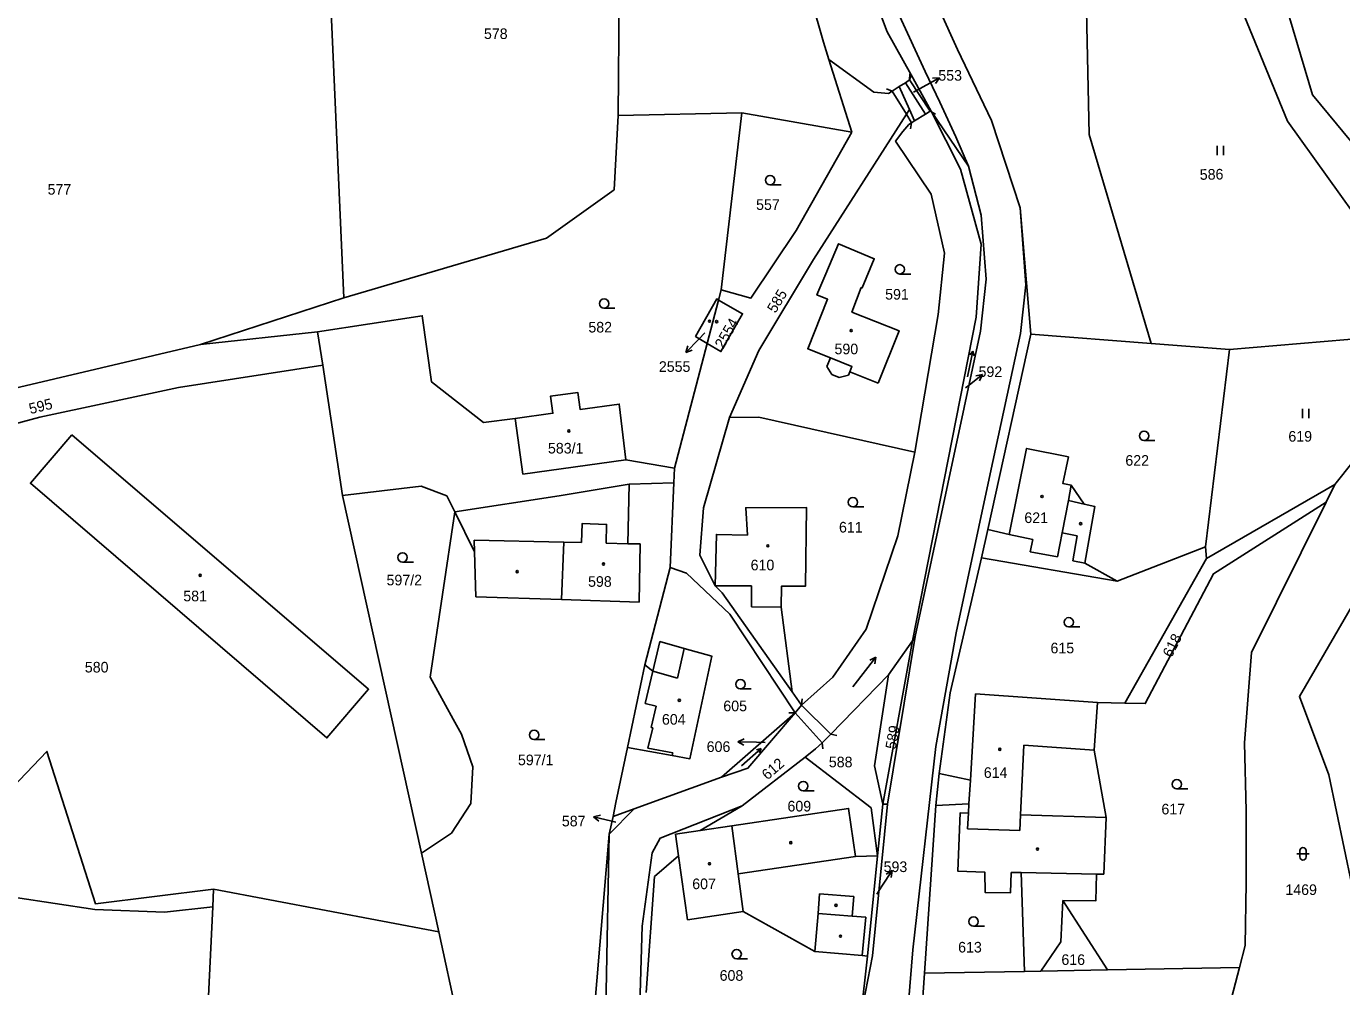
# Model space of a CAD drawing. Extents: x -520431 to -517205, y -1075927 to -1074013.
# Drawn here: x -518044.1 to -517833.2, y -1075835.4 to -1075681.5 of the extents above; entities that cross this region are included whole.
import ezdxf

# ---------------------------------------------------------------- set-up
doc = ezdxf.new("R2010")
doc.units = 0
for name, color, linetype in [('Hranice parcel', 7, 'Continuous'), ('Parcelní čísla', 7, 'Continuous'), ('Pop  PČ popisy', 7, 'Continuous'), ('Vnitřní kresba', 7, 'Continuous'), ('Značky budov', 7, 'Continuous'), ('Značky kultur', 7, 'Continuous')]:
    doc.layers.add(name, color=color, linetype=linetype)

msp = doc.modelspace()

# ---------------------------------------------------------------- linework, layer by layer
at = {"layer": 'Hranice parcel'}
for p, q in [((-517993.21, -1075725.03), (-517996.53, -1075648.79)), ((-517949.22, -1075695.82), (-517948.93, -1075661.56)), ((-517841.94, -1075696.76), (-517852.53, -1075670.8)), ((-517911.76, -1075698.48), (-517915.44, -1075686.85)), ((-517902.27, -1075689.29), (-517902.5, -1075690.13)), ((-517899.03, -1075695.13), (-517902.27, -1075689.29)), ((-517904.17, -1075691.2), (-517905.29, -1075691.92)), ((-517902.52, -1075694.85), (-517904.17, -1075691.2)), ((-517902.5, -1075690.13), (-517903.18, -1075690.57)), ((-517903.18, -1075690.57), (-517899.98, -1075695.6)), ((-517929.4, -1075695.38), (-517949.22, -1075695.82)), ((-517932.68, -1075723.77), (-517929.4, -1075695.38)), ((-517929.4, -1075695.38), (-517911.76, -1075698.48)), ((-517901.7, -1075696.68), (-517902.52, -1075694.85)), ((-517899.98, -1075695.6), (-517899.22, -1075695.12)), ((-517899.22, -1075695.12), (-517899.03, -1075695.13)), ((-517899.03, -1075695.13), (-517893.06, -1075703.93)), ((-517902.19, -1075696.98), (-517901.7, -1075696.68)), ((-517884.79, -1075710.63), (-517883.07, -1075730.86)), ((-517993.21, -1075725.03), (-517960.71, -1075715.51)), ((-518016.17, -1075732.51), (-517993.21, -1075725.03)), ((-517933.11, -1075725.4), (-517934.94, -1075732.35)), ((-517933.11, -1075725.4), (-517932.68, -1075723.77)), ((-518016.17, -1075732.51), (-517997.43, -1075730.48)), ((-517996.55, -1075735.82), (-517997.43, -1075730.48)), ((-517883.07, -1075730.86), (-517889.97, -1075762.15)), ((-517883.07, -1075730.86), (-517863.8, -1075732.34)), ((-517851.25, -1075733.31), (-517814.81, -1075730.26)), ((-517834.35, -1075754.98), (-517814.81, -1075730.26)), ((-517940.21, -1075752.33), (-517934.94, -1075732.35)), ((-517863.8, -1075732.34), (-517851.25, -1075733.31)), ((-517851.25, -1075733.31), (-517855.06, -1075764.95)), ((-517993.41, -1075756.71), (-517996.55, -1075735.82)), ((-517940.21, -1075752.33), (-517940.31, -1075754.67)), ((-517947.65, -1075764.44), (-517947.45, -1075754.88)), ((-517947.45, -1075754.88), (-517940.31, -1075754.67)), ((-517940.31, -1075754.67), (-517940.86, -1075768.28)), ((-517834.35, -1075754.98), (-517854.94, -1075766.83)), ((-517835.74, -1075757.77), (-517834.35, -1075754.98)), ((-517980.74, -1075814.02), (-517993.41, -1075756.71)), ((-517976.66, -1075756.75), (-517975.38, -1075759.36)), ((-517975.38, -1075759.36), (-517979.33, -1075785.85)), ((-517847.7, -1075781.86), (-517835.74, -1075757.77)), ((-517889.97, -1075762.15), (-517890.98, -1075766.71)), ((-517886.56, -1075762.97), (-517889.97, -1075762.15)), ((-517945.69, -1075764.49), (-517947.65, -1075764.44)), ((-517855.06, -1075764.95), (-517869.22, -1075770.43)), ((-517854.94, -1075766.83), (-517855.06, -1075764.95)), ((-517869.22, -1075770.43), (-517890.98, -1075766.71)), ((-517867.99, -1075789.98), (-517854.94, -1075766.83)), ((-517944.96, -1075783.88), (-517940.86, -1075768.28)), ((-517932.55, -1075772.33), (-517933.66, -1075771.19)), ((-517921.32, -1075788.19), (-517932.55, -1075772.33)), ((-517921.32, -1075788.19), (-517923.07, -1075774.62)), ((-517902.04, -1075780.02), (-517906.77, -1075806.18)), ((-517905.88, -1075785.45), (-517902.04, -1075780.02)), ((-517947.72, -1075797.08), (-517944.96, -1075783.88)), ((-517905.88, -1075785.45), (-517915.14, -1075794.96)), ((-517919.82, -1075790.31), (-517921.32, -1075788.19)), ((-517920.87, -1075791.55), (-517919.82, -1075790.31)), ((-517872.41, -1075789.88), (-517867.99, -1075789.98)), ((-517932.66, -1075801.83), (-517920.87, -1075791.55)), ((-517915.14, -1075794.96), (-517916.53, -1075796.35)), ((-517917.58, -1075797.32), (-517919.26, -1075798.63)), ((-517916.53, -1075796.35), (-517917.58, -1075797.32)), ((-517919.26, -1075798.63), (-517929.33, -1075806.46)), ((-517897.78, -1075801.27), (-517898.31, -1075806.39)), ((-517932.66, -1075801.83), (-517946.65, -1075806.94)), ((-517946.65, -1075806.94), (-517950.64, -1075810.98)), ((-517946.65, -1075806.94), (-517950.02, -1075808.15)), ((-517936.09, -1075810.39), (-517929.33, -1075806.46)), ((-517907.64, -1075814.45), (-517906.77, -1075806.18)), ((-517898.31, -1075806.39), (-517900.13, -1075833.28)), ((-517950.64, -1075810.98), (-517950.02, -1075808.15)), ((-517975.91, -1075810.85), (-517980.74, -1075814.02)), ((-517954.08, -1075851.68), (-517950.64, -1075810.98)), ((-517940.01, -1075810.97), (-517936.09, -1075810.39)), ((-517939.52, -1075814.46), (-517940.01, -1075810.97)), ((-517977.95, -1075826.65), (-517980.74, -1075814.02)), ((-517938.08, -1075824.71), (-517939.52, -1075814.46)), ((-517907.64, -1075814.45), (-517909.25, -1075830.52)), ((-517872.55, -1075817.38), (-517871.37, -1075817.4)), ((-518014.08, -1075819.78), (-518014.21, -1075822.61)), ((-518014.08, -1075819.78), (-517977.95, -1075826.65)), ((-518014.21, -1075822.61), (-518015.72, -1075854.53)), ((-517878.25, -1075828.22), (-517877.96, -1075821.6)), ((-517870.79, -1075832.75), (-517877.96, -1075821.6)), ((-517972.81, -1075850.25), (-517977.95, -1075826.65)), ((-517881.49, -1075832.94), (-517878.25, -1075828.22)), ((-517910.33, -1075840.11), (-517909.25, -1075830.52)), ((-517900.13, -1075833.28), (-517884.06, -1075832.99)), ((-517884.06, -1075832.99), (-517881.49, -1075832.94)), ((-517881.49, -1075832.94), (-517870.79, -1075832.75)), ((-517870.79, -1075832.75), (-517849.63, -1075832.36)), ((-517900.13, -1075833.28), (-517901.7, -1075856.5))]:
    msp.add_line(p, q, dxfattribs=at)
for points in [[(-517806.36, -1075723.7), (-517819.22, -1075715.13), (-517837.94, -1075692.54), (-517847.81, -1075659.24), (-517846.75, -1075648.71), (-517851.31, -1075636.96), (-517844.3, -1075608.48), (-517829.48, -1075581.32), (-517717.18, -1075576.77), (-517716.55, -1075569.07)], [(-517893.06, -1075703.93), (-517895.1, -1075699.24), (-517897.65, -1075693.7), (-517900.03, -1075688.77), (-517908.54, -1075670.21), (-517911.85, -1075659.26), (-517913.67, -1075650.22), (-517914.9, -1075634.97), (-517914.4, -1075623.91), (-517911.26, -1075603.96), (-517910.57, -1075599.74)], [(-517915.44, -1075686.85), (-517916.32, -1075684.08), (-517922.24, -1075663.35)], [(-517902.93, -1075667.29), (-517894.81, -1075685.27), (-517889.37, -1075696.64), (-517884.79, -1075710.63)], [(-517910.5, -1075670.78), (-517906.1, -1075682.41), (-517902.27, -1075689.29)], [(-517863.8, -1075732.34), (-517873.73, -1075698.85), (-517874.32, -1075671.54), (-517852.53, -1075670.8)], [(-517905.29, -1075691.92), (-517905.88, -1075692.3), (-517908.25, -1075692.1), (-517915.44, -1075686.85)], [(-517960.71, -1075715.51), (-517949.84, -1075707.72), (-517949.22, -1075695.82)], [(-517917.9, -1075718.88), (-517903.02, -1075695.63), (-517902.52, -1075694.85)], [(-517902.04, -1075780.02), (-517891.86, -1075728.13), (-517891.01, -1075716.47), (-517894.33, -1075704.44), (-517899.03, -1075695.13)], [(-517901.68, -1075749.78), (-517897.91, -1075727.73), (-517896.9, -1075717.9), (-517899.07, -1075708.43), (-517904.74, -1075699.94), (-517903.57, -1075698.4), (-517902.61, -1075697.25), (-517902.19, -1075696.98)], [(-517806.36, -1075723.7), (-517817.71, -1075723.13), (-517829.2, -1075714.45), (-517841.94, -1075696.76)], [(-517911.76, -1075698.48), (-517920.71, -1075714.27), (-517927.94, -1075725.08), (-517932.68, -1075723.77)], [(-517893.06, -1075703.93), (-517891.02, -1075711.82), (-517890.23, -1075722.07), (-517891.16, -1075730.37), (-517901.63, -1075779.34), (-517902.04, -1075780.02)], [(-517884.79, -1075710.63), (-517883.87, -1075722.94), (-517884.72, -1075730.77), (-517889.6, -1075753.25), (-517895.04, -1075778.71), (-517898.3, -1075796.92), (-517902.01, -1075829.51), (-517907.51, -1075896.83), (-517907.86, -1075903.34), (-517907.69, -1075911.23), (-517906.74, -1075925.35)], [(-517907.55, -1075738.73), (-517912.09, -1075736.92), (-517911.74, -1075736.06), (-517915.2, -1075734.66), (-517918.82, -1075733.2), (-517915.64, -1075725.28), (-517917.37, -1075724.59), (-517915.94, -1075721.18), (-517913.92, -1075716.38), (-517908.16, -1075718.78), (-517910.09, -1075723.46), (-517910.24, -1075723.4), (-517911.76, -1075727.33), (-517904.2, -1075730.33), (-517907.55, -1075738.73)], [(-517931.35, -1075744.24), (-517926.65, -1075733.5), (-517917.9, -1075718.88)], [(-517934.94, -1075732.35), (-517936.81, -1075731.23), (-517933.42, -1075725.22), (-517933.11, -1075725.4)], [(-517933.11, -1075725.4), (-517929.27, -1075727.6), (-517932.75, -1075733.67), (-517934.94, -1075732.35)], [(-517793.8, -1075846.26), (-517812.91, -1075845.37), (-517821.92, -1075843.14), (-517831.6, -1075819.12), (-517835.29, -1075801.49), (-517840.01, -1075788.94), (-517813.28, -1075742.89), (-517811.29, -1075727.53)], [(-517997.43, -1075730.48), (-517980.63, -1075727.91), (-517979.12, -1075738.52), (-517970.81, -1075745.04), (-517965.72, -1075744.37)], [(-518086.69, -1075751.28), (-518055.42, -1075741.77), (-518016.17, -1075732.51)], [(-517996.55, -1075735.82), (-518019.67, -1075739.43), (-518041.93, -1075744.18), (-518084.83, -1075755.71)], [(-517965.72, -1075744.37), (-517959.68, -1075743.55), (-517960.06, -1075740.79), (-517955.68, -1075740.24), (-517955.31, -1075742.92), (-517949.03, -1075742.06), (-517947.96, -1075751.03), (-517940.21, -1075752.33)], [(-517933.66, -1075771.19), (-517936.12, -1075766.26), (-517935.54, -1075758.68), (-517931.35, -1075744.24)], [(-517931.35, -1075744.24), (-517926.67, -1075744.16), (-517901.68, -1075749.78)], [(-518036.76, -1075747.01), (-517989.23, -1075787.77), (-517995.9, -1075795.56), (-518043.41, -1075754.75), (-518036.76, -1075747.01)], [(-517919.82, -1075790.31), (-517914.79, -1075785.83), (-517909.45, -1075778.12), (-517904.4, -1075763.17), (-517901.68, -1075749.78)], [(-517869.22, -1075770.43), (-517874.43, -1075767.58), (-517872.82, -1075758.48), (-517874.53, -1075758.09), (-517876.58, -1075755.08), (-517877.93, -1075754.8), (-517877.06, -1075750.54), (-517883.74, -1075749.18), (-517886.56, -1075762.97)], [(-517947.45, -1075754.88), (-517958.69, -1075756.76), (-517975.38, -1075759.36)], [(-517993.41, -1075756.71), (-517980.77, -1075755.23), (-517976.66, -1075756.75)], [(-518085.54, -1075758.24), (-518089.97, -1075774.12), (-518081.15, -1075797.65), (-518067.69, -1075810.01), (-518055.06, -1075812.63), (-518040.79, -1075797.74), (-518033, -1075822.13), (-518014.08, -1075819.78)], [(-517975.38, -1075759.36), (-517972.26, -1075765.74), (-517972.05, -1075772.98)], [(-517923.07, -1075774.62), (-517923.05, -1075771.25), (-517919.21, -1075771.26), (-517919.03, -1075758.63), (-517928.77, -1075758.67), (-517928.51, -1075763.07), (-517933.48, -1075762.96), (-517933.66, -1075771.19)], [(-517835.74, -1075757.77), (-517853.77, -1075769.27), (-517864.72, -1075790.06), (-517867.99, -1075789.98)], [(-518014.21, -1075822.61), (-518021.91, -1075823.46), (-518033.09, -1075823.04), (-518071.28, -1075817.31), (-518096.56, -1075777.81), (-518098.94, -1075763.48)], [(-517972.05, -1075772.98), (-517958.3, -1075773.41), (-517945.87, -1075773.79), (-517945.69, -1075764.49)], [(-517890.98, -1075766.71), (-517895.98, -1075788.35), (-517897.78, -1075801.27)], [(-517940.86, -1075768.28), (-517938.26, -1075769.18), (-517931.33, -1075775.75), (-517920.87, -1075791.55)], [(-517947.72, -1075797.08), (-517940.56, -1075798.39), (-517937.72, -1075798.91), (-517934.19, -1075782.47), (-517938.63, -1075781.22), (-517942.53, -1075780.13), (-517943.66, -1075784.85), (-517944.96, -1075783.88)], [(-517849.63, -1075832.36), (-517848.71, -1075828.85), (-517848.54, -1075818.76), (-517848.53, -1075807.23), (-517848.85, -1075796.35), (-517847.7, -1075781.86)], [(-517979.33, -1075785.85), (-517975.66, -1075792.57), (-517974.34, -1075794.95), (-517972.49, -1075800.22), (-517972.82, -1075806.05), (-517975.91, -1075810.85)], [(-517906.77, -1075806.18), (-517908.15, -1075800.03), (-517905.88, -1075785.45)], [(-517872.41, -1075789.88), (-517891.94, -1075788.52), (-517892.76, -1075802.31), (-517897.78, -1075801.27)], [(-517871.37, -1075817.4), (-517871.02, -1075808.34), (-517872.94, -1075797.51), (-517872.41, -1075789.88)], [(-517920.87, -1075791.55), (-517928.43, -1075800.4), (-517932.66, -1075801.83)], [(-517950.02, -1075808.15), (-517949.57, -1075805.9), (-517947.72, -1075797.08)], [(-517919.26, -1075798.63), (-517908.67, -1075806.79), (-517907.64, -1075814.45)], [(-517929.33, -1075806.46), (-517942.46, -1075811.62), (-517943.78, -1075813.96), (-517945.36, -1075825.71), (-517945.71, -1075836.51), (-517947.05, -1075848.01), (-517943.76, -1075852.31), (-517939.4, -1075856.27)], [(-517936.09, -1075810.39), (-517931.02, -1075809.64), (-517912.28, -1075806.85), (-517911.15, -1075814.58), (-517907.64, -1075814.45)], [(-517906.77, -1075806.18), (-517906.07, -1075806.2), (-517908.44, -1075830.49), (-517910.33, -1075840.11)], [(-517886.24, -1075817.12), (-517886.35, -1075820.39), (-517890.4, -1075820.31), (-517890.44, -1075817.08), (-517894.75, -1075816.92), (-517894.42, -1075807.59), (-517893.08, -1075807.64), (-517892.99, -1075806.14), (-517898.31, -1075806.39)], [(-517950.64, -1075810.98), (-517951.13, -1075836.2), (-517951.2, -1075843.92), (-517949.99, -1075851.99), (-517946.83, -1075856.79), (-517945.64, -1075856.63), (-517935.1, -1075861.62)], [(-517944.73, -1075836.35), (-517943.41, -1075817.79), (-517939.52, -1075814.46)], [(-517884.06, -1075832.99), (-517884.62, -1075817.15), (-517886.24, -1075817.12)], [(-517877.96, -1075821.6), (-517872.64, -1075821.66), (-517872.55, -1075817.38)], [(-517909.25, -1075830.52), (-517910.12, -1075830.45), (-517917.68, -1075829.78), (-517929.16, -1075823.37), (-517938.08, -1075824.71)], [(-517853.06, -1075850.94), (-517852.26, -1075842.4), (-517849.63, -1075832.36)]]:
    msp.add_lwpolyline(points, dxfattribs=at)
at = {"layer": 'Pop  PČ popisy'}
for p, q in [((-517900.34, -1075691.24), (-517897.72, -1075689.78)), ((-517897.72, -1075689.78), (-517898.83, -1075689.83)), ((-517897.72, -1075689.78), (-517898.35, -1075690.71)), ((-517901.86, -1075692.1), (-517900.34, -1075691.24)), ((-517936.3, -1075731.66), (-517938.39, -1075733.82)), ((-517935.32, -1075730.65), (-517936.3, -1075731.66)), ((-517938.39, -1075733.82), (-517938.05, -1075732.75)), ((-517938.39, -1075733.82), (-517937.33, -1075733.45)), ((-517893.17, -1075739.19), (-517890.8, -1075737.34)), ((-517890.8, -1075737.34), (-517891.9, -1075737.56)), ((-517890.8, -1075737.34), (-517891.29, -1075738.35)), ((-517893.54, -1075739.48), (-517893.17, -1075739.19)), ((-517930.03, -1075796.17), (-517929.01, -1075795.7)), ((-517927.03, -1075796.27), (-517930.03, -1075796.17)), ((-517930.03, -1075796.17), (-517929.05, -1075796.7)), ((-517925.65, -1075796.31), (-517927.03, -1075796.27)), ((-517953.15, -1075808.2), (-517952.06, -1075807.96)), ((-517950.24, -1075808.93), (-517953.15, -1075808.2)), ((-517953.15, -1075808.2), (-517952.3, -1075808.93)), ((-517949.61, -1075809.09), (-517950.24, -1075808.93)), ((-517906.95, -1075819.34), (-517905.32, -1075816.82)), ((-517905.32, -1075816.82), (-517906.28, -1075817.39)), ((-517905.32, -1075816.82), (-517905.44, -1075817.94)), ((-517907.78, -1075820.61), (-517906.95, -1075819.34))]:
    msp.add_line(p, q, dxfattribs=at)
at = {"layer": 'Vnitřní kresba'}
for p, q in [((-517902.47, -1075689.13), (-517902.5, -1075690.13)), ((-517906.22, -1075691.56), (-517905.29, -1075691.92)), ((-517904.17, -1075691.2), (-517903.18, -1075690.57)), ((-517899.22, -1075695.12), (-517902.5, -1075690.13)), ((-517903.02, -1075695.63), (-517905.29, -1075691.92)), ((-517902.19, -1075696.98), (-517903.02, -1075695.63)), ((-517901.7, -1075696.68), (-517899.98, -1075695.6)), ((-517898.35, -1075695.62), (-517899.22, -1075695.12)), ((-517902.36, -1075697.97), (-517902.19, -1075696.98)), ((-517915.75, -1075736.05), (-517915.2, -1075734.66)), ((-517914.99, -1075737.34), (-517915.75, -1075736.05)), ((-517913.8, -1075737.83), (-517914.99, -1075737.34)), ((-517912.3, -1075737.44), (-517913.8, -1075737.83)), ((-517912.09, -1075736.92), (-517912.3, -1075737.44)), ((-517964.5, -1075753.28), (-517965.72, -1075744.37)), ((-517947.96, -1075751.03), (-517964.5, -1075753.28)), ((-517876.58, -1075755.08), (-517877.05, -1075757.52)), ((-517877.05, -1075757.52), (-517878.05, -1075762.71)), ((-517877.05, -1075757.52), (-517874.53, -1075758.09)), ((-517886.56, -1075762.97), (-517882.73, -1075763.75)), ((-517878.79, -1075766.57), (-517878.05, -1075762.71)), ((-517878.05, -1075762.71), (-517875.64, -1075763.17)), ((-517875.64, -1075763.17), (-517876.34, -1075767.17)), ((-517972.26, -1075765.74), (-517972.32, -1075763.86)), ((-517972.32, -1075763.86), (-517957.9, -1075764.21)), ((-517958.3, -1075773.41), (-517957.9, -1075764.21)), ((-517957.9, -1075764.21), (-517955.08, -1075764.27)), ((-517951.15, -1075764.37), (-517947.65, -1075764.44)), ((-517882.73, -1075763.75), (-517883.17, -1075765.73)), ((-517883.17, -1075765.73), (-517878.79, -1075766.57)), ((-517876.34, -1075767.17), (-517874.43, -1075767.58)), ((-517927.85, -1075771.22), (-517933.66, -1075771.19)), ((-517927.87, -1075774.57), (-517927.85, -1075771.22)), ((-517923.07, -1075774.62), (-517927.87, -1075774.57)), ((-517901.63, -1075779.34), (-517906.07, -1075806.2)), ((-517938.63, -1075781.22), (-517939.72, -1075786)), ((-517943.66, -1075784.85), (-517944.9, -1075790.04)), ((-517939.72, -1075786), (-517943.66, -1075784.85)), ((-517944.9, -1075790.04), (-517943.12, -1075790.47)), ((-517943.12, -1075790.47), (-517943.93, -1075793.88)), ((-517919.73, -1075789.31), (-517919.82, -1075790.31)), ((-517915.14, -1075794.96), (-517919.82, -1075790.31)), ((-517921.87, -1075791.57), (-517920.87, -1075791.55)), ((-517916.53, -1075796.35), (-517920.87, -1075791.55)), ((-517943.68, -1075793.94), (-517944.46, -1075797.23)), ((-517943.93, -1075793.88), (-517943.68, -1075793.94)), ((-517914.16, -1075795.17), (-517915.14, -1075794.96)), ((-517944.46, -1075797.23), (-517940.48, -1075797.95)), ((-517916.43, -1075797.34), (-517916.53, -1075796.35)), ((-517884.19, -1075796.72), (-517884.71, -1075807.9)), ((-517872.94, -1075797.51), (-517884.19, -1075796.72)), ((-517940.48, -1075797.95), (-517940.56, -1075798.39)), ((-517892.76, -1075802.31), (-517892.99, -1075806.14)), ((-517893.08, -1075807.64), (-517893.23, -1075810.14)), ((-517931.02, -1075809.64), (-517929.96, -1075817.37)), ((-517884.83, -1075810.4), (-517884.71, -1075807.9)), ((-517884.71, -1075807.9), (-517871.02, -1075808.34)), ((-517893.23, -1075810.14), (-517884.83, -1075810.4)), ((-517929.96, -1075817.37), (-517911.15, -1075814.58)), ((-517929.96, -1075817.37), (-517929.16, -1075823.37)), ((-517884.62, -1075817.15), (-517872.55, -1075817.38)), ((-517917.15, -1075823.68), (-517916.93, -1075820.55)), ((-517916.93, -1075820.55), (-517911.45, -1075820.99)), ((-517911.45, -1075820.99), (-517911.7, -1075824.12)), ((-517917.68, -1075829.78), (-517917.15, -1075823.68)), ((-517917.15, -1075823.68), (-517911.7, -1075824.12)), ((-517911.7, -1075824.12), (-517909.51, -1075824.3)), ((-517909.51, -1075824.3), (-517910.12, -1075830.45))]:
    msp.add_line(p, q, dxfattribs=at)
msp.add_lwpolyline([(-517955.08, -1075764.27), (-517955, -1075761.23), (-517951.08, -1075761.35), (-517951.15, -1075764.37)], dxfattribs=at)
at = {"layer": 'Značky budov'}
for centre in [(-517934.58, -1075728.78), (-517933.43, -1075728.85), (-517911.86, -1075730.29), (-517957.12, -1075746.37), (-517881.27, -1075756.88), (-517875.09, -1075761.23), (-517925.22, -1075764.79), (-517951.56, -1075767.7), (-518016.22, -1075769.5), (-517965.41, -1075768.91), (-517939.42, -1075789.54), (-517888.05, -1075797.39), (-517921.55, -1075812.36), (-517882, -1075813.38), (-517934.58, -1075815.73), (-517914.3, -1075822.4), (-517913.58, -1075827.34)]:
    msp.add_circle(centre, 0.175, dxfattribs=at)
at = {"layer": 'Značky kultur'}
for p, q in [((-517853.21, -1075702.21), (-517853.21, -1075700.71)), ((-517852.21, -1075702.21), (-517852.21, -1075700.71)), ((-517924.86, -1075706.94), (-517923.11, -1075706.94)), ((-517904.08, -1075721.23), (-517902.33, -1075721.23)), ((-517951.48, -1075726.72), (-517949.73, -1075726.72)), ((-517893.23, -1075737.71), (-517892.36, -1075733.6)), ((-517892.36, -1075733.6), (-517892.84, -1075734.2)), ((-517892.36, -1075733.6), (-517892.15, -1075734.35)), ((-517839.52, -1075744.33), (-517839.52, -1075742.83)), ((-517838.52, -1075744.33), (-517838.52, -1075742.83)), ((-517864.92, -1075747.91), (-517863.17, -1075747.91)), ((-517911.59, -1075758.55), (-517909.84, -1075758.55)), ((-517983.77, -1075767.4), (-517982.02, -1075767.4)), ((-517876.99, -1075777.79), (-517875.24, -1075777.79)), ((-517911.59, -1075787.37), (-517907.9, -1075782.64)), ((-517907.9, -1075782.64), (-517908.89, -1075783.1)), ((-517907.9, -1075782.64), (-517908.1, -1075783.72)), ((-517929.63, -1075787.71), (-517927.88, -1075787.71)), ((-517962.7, -1075795.83), (-517960.95, -1075795.83)), ((-517929.44, -1075800.02), (-517926.27, -1075797.27)), ((-517926.27, -1075797.27), (-517927.02, -1075797.45)), ((-517926.27, -1075797.27), (-517926.56, -1075797.98)), ((-517919.55, -1075804.03), (-517917.8, -1075804.03)), ((-517859.67, -1075803.73), (-517857.92, -1075803.73)), ((-517840.45, -1075814.13), (-517838.45, -1075814.13)), ((-517839.95, -1075813.63), (-517839.95, -1075814.63)), ((-517838.95, -1075814.63), (-517838.95, -1075813.63)), ((-517892.25, -1075825.74), (-517890.5, -1075825.74)), ((-517930.22, -1075830.96), (-517928.47, -1075830.96))]:
    msp.add_line(p, q, dxfattribs=at)
for centre in [(-517924.86, -1075706.19), (-517904.08, -1075720.48), (-517951.48, -1075725.97), (-517864.92, -1075747.16), (-517911.59, -1075757.8), (-517983.77, -1075766.65), (-517876.99, -1075777.04), (-517929.63, -1075786.96), (-517962.7, -1075795.08), (-517919.55, -1075803.28), (-517859.67, -1075802.98), (-517892.25, -1075824.99), (-517930.22, -1075830.21)]:
    msp.add_circle(centre, 0.75, dxfattribs=at)
for centre, start, end in [((-517839.45, -1075813.63), 0, 180), ((-517839.45, -1075814.63), 180, 359.9879)]:
    msp.add_arc(centre, 0.5, start, end, dxfattribs=at)

# ---------------------------------------------------------------- texts
at = {"layer": 'Parcelní čísla'}
for s, p in [('578', (-517970.73, -1075683.57)), ('553', (-517897.9, -1075690.25)), ('577', (-518040.67, -1075708.51)), ('557', (-517927.11, -1075710.96)), ('591', (-517906.42, -1075725.33)), ('582', (-517953.99, -1075730.6)), ('590', (-517914.54, -1075734.09)), ('2555', (-517942.69, -1075736.91)), ('592', (-517891.45, -1075737.73)), ('619', (-517841.79, -1075748.09)), ('583/1', (-517960.47, -1075749.99)), ('622', (-517867.92, -1075751.95)), ('611', (-517913.82, -1075762.65)), ('621', (-517884.11, -1075761.13)), ('610', (-517927.98, -1075768.71)), ('597/2', (-517986.34, -1075771.12)), ('598', (-517954.04, -1075771.35)), ('581', (-518018.92, -1075773.68)), ('615', (-517879.92, -1075782.01)), ('580', (-518034.7, -1075785.08)), ('605', (-517932.36, -1075791.29)), ('604', (-517942.2, -1075793.44)), ('606', (-517935.03, -1075797.81)), ('597/1', (-517965.28, -1075799.94)), ('588', (-517915.45, -1075800.27)), ('614', (-517890.61, -1075801.97)), ('609', (-517922.08, -1075807.35)), ('617', (-517862.14, -1075807.82)), ('587', (-517958.24, -1075809.74)), ('593', (-517906.67, -1075817.06)), ('607', (-517937.34, -1075819.8)), ('1469', (-517842.27, -1075820.73)), ('613', (-517894.72, -1075829.95)), ('616', (-517878.17, -1075831.94)), ('608', (-517932.95, -1075834.48))]:
    msp.add_text(s, height=1.7, dxfattribs=at).set_placement(p)
for s, rotation, p in [('586', 1, (-517855.98, -1075706.14)), ('585', 59, (-517924, -1075727.61)), ('2554', 60, (-517932.37, -1075733.33)), ('595', 14, (-518043.42, -1075743.69)), ('618', 63, (-517860.52, -1075782.8)), ('589', 80, (-517904.73, -1075797.47)), ('612', 41, (-517925.29, -1075802.4))]:
    msp.add_text(s, height=1.7, rotation=rotation, dxfattribs=at).set_placement(p)

doc.saveas('drawing.dxf')
